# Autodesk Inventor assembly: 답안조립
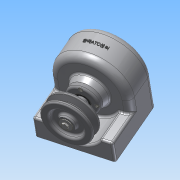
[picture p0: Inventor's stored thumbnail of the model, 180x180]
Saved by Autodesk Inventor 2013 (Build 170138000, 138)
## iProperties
Created: 2015-02
Part Number: 답안조립
Document SubType Name: Assembly
Designer: Administrator
Author: Administrator
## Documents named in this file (14)
- C:\Documents and Settings\Administrator\바탕 화면\450214V1020\답안조립.iam
- C:\Documents and Settings\Administrator\바탕 화면\450214V1020\1-본체.ipt
- C:\Documents and Settings\Administrator\바탕 화면\450214V1020\베어링 6001.ipt
- C:\Documents and Settings\Administrator\바탕 화면\450214V1020\축.ipt
- C:\Documents and Settings\Administrator\바탕 화면\450214V1020\키5x5.ipt
- C:\Documents and Settings\Administrator\바탕 화면\450214V1020\키4x4.ipt
- C:\Documents and Settings\Administrator\바탕 화면\450214V1020\스퍼기어.ipt
- C:\Documents and Settings\Administrator\바탕 화면\450214V1020\축커버.ipt
- C:\Documents and Settings\Administrator\바탕 화면\450214V1020\M3x0.5.ipt
- C:\Documents and Settings\Administrator\바탕 화면\450214V1020\오일실.ipt
- C:\Documents and Settings\Administrator\바탕 화면\450214V1020\4-벨트풀리.ipt
- C:\Documents and Settings\Administrator\바탕 화면\450214V1020\와샤.ipt
- C:\Documents and Settings\Administrator\바탕 화면\450214V1020\M5x0.8.ipt
- M5x0.8.ipt
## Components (7 placed, 4 different names)
1. 1-본체:1
2. 4-벨트풀리:1 — 각도:4
3. M5x0.8:1 — 각도:5
4. M3x0.5:1
5. M3x0.5:2
6. M3x0.5:3
7. M3x0.5:4
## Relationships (2: Angle 2)
- 각도:4 [Angle]: 4-벨트풀리:1
- 각도:5 [Angle]: M5x0.8:1
